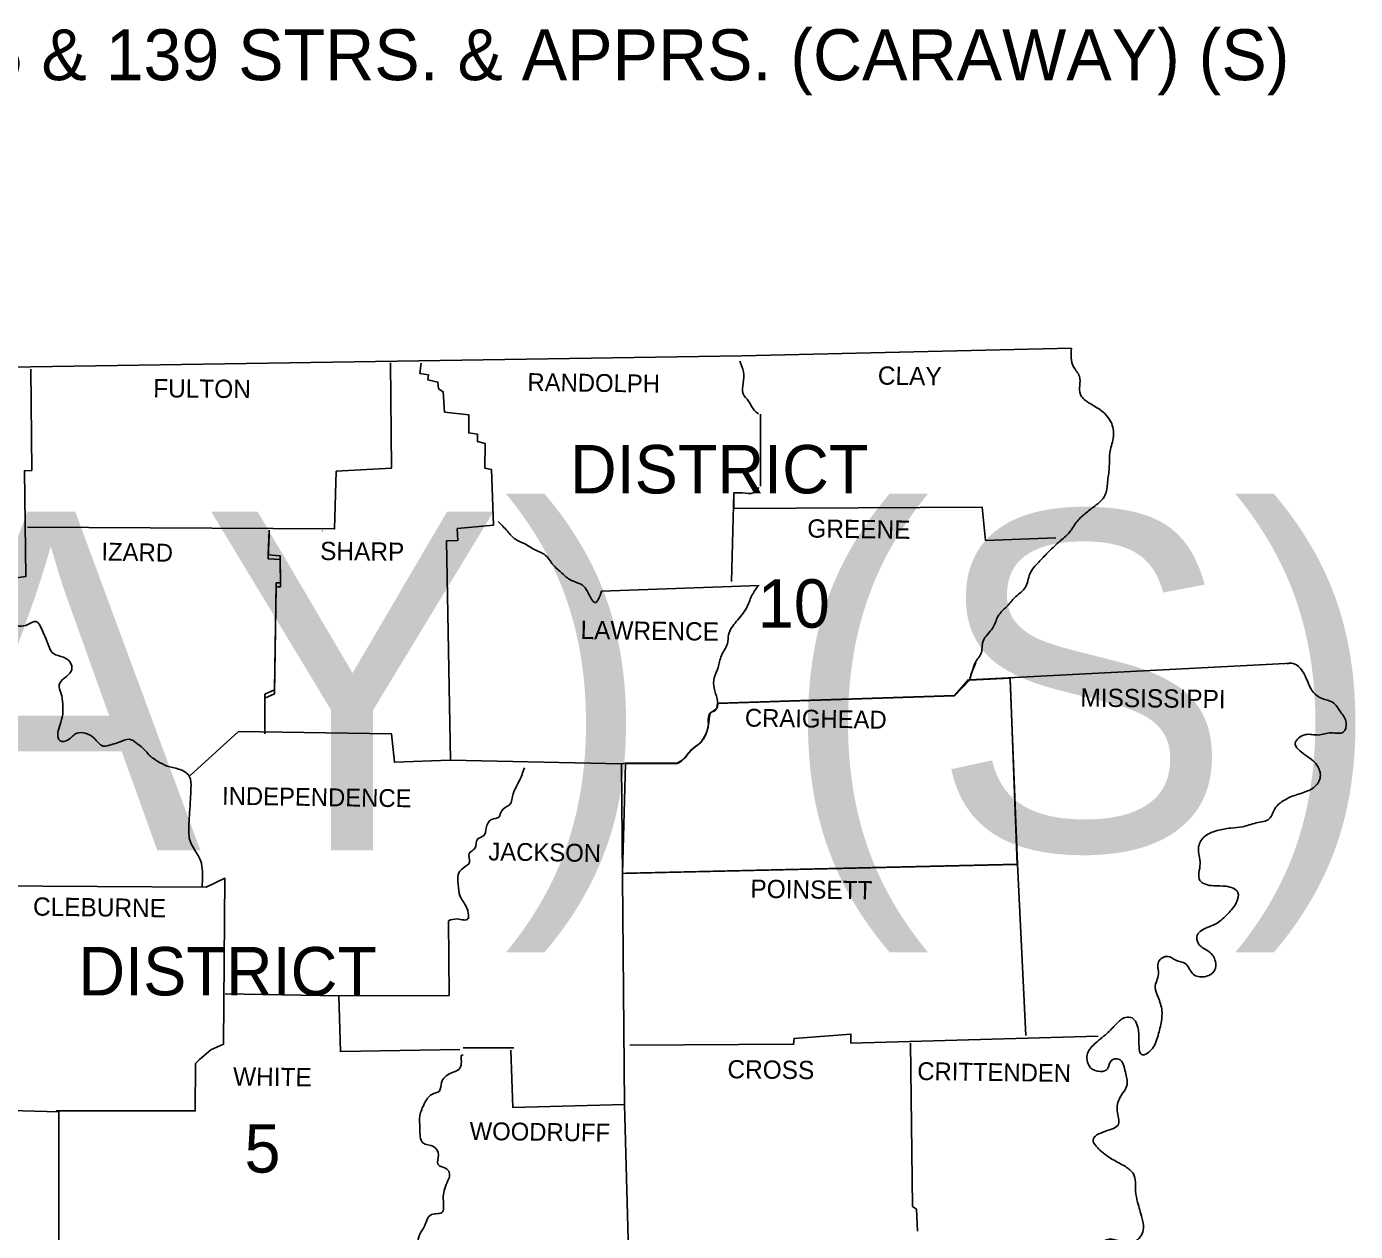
# Model space of a CAD drawing. Extents: x 166 to 3995, y -61 to 2074.
# Drawn here: x 2999.8 to 3305.9, y 1757.5 to 2035 of the extents above; entities that cross this region are included whole.
import ezdxf

# ---------------------------------------------------------------- set-up
doc = ezdxf.new("R2010")
doc.units = 0
for name, color, linetype in [('1', 7, 'Continuous'), ('2', 7, 'Continuous'), ('3', 7, 'Continuous'), ('R_Border', 7, 'Continuous'), ('S_MISC_BOUNDARY', 7, 'Continuous')]:
    doc.layers.add(name, color=color, linetype=linetype)

msp = doc.modelspace()

# ---------------------------------------------------------------- linework, layer by layer
at = {"layer": '1'}
for p, q in [((3216.98, 1884.51), (3218.15, 1888.13)), ((3217.27, 1885.68), (3218.45, 1888.52)), ((3100.35, 1799.78), (3112, 1799.78))]:
    msp.add_line(p, q, dxfattribs=at)
for points in [[(2703.71, 1956.42), (2861.92, 1956.32), (3000.75, 1956.61), (3164.54, 1959.16), (3240.46, 1960.92)], [(3083.62, 1957.49), (3083.82, 1933.23), (3071.1, 1932.55), (3070.71, 1919.24), (2999.97, 1919.63)], [(3090.67, 1957.4), (3090.37, 1955.05), (3092.33, 1954.76), (3092.23, 1953.58), (3094.48, 1953.09), (3094.68, 1951.53), (3095.75, 1950.84), (3096.05, 1946.15), (3101.63, 1945.56), (3101.63, 1941.35), (3103.68, 1941.06), (3103.68, 1939.39), (3105.44, 1938.9), (3105.34, 1933.23), (3106.91, 1932.94), (3107.3, 1920.12), (3098.98, 1919.34), (3099.08, 1916.6), (3096.54, 1916.5), (3097.42, 1866.01), (3136.85, 1865.13), (3137.53, 1786.66), (3111.8, 1785.98), (3111.31, 1799.19)], [(3000.75, 1956.03), (3000.95, 1932.74), (2999.28, 1932.64), (2999.58, 1908.28), (2992.73, 1907.3), (2993.32, 1900.75), (2995.66, 1897.71), (2995.47, 1889.98), (2982.16, 1889.5), (2981.67, 1877.56), (2969.54, 1877.17), (2968.95, 1862.69), (2969.64, 1861.51), (2969.93, 1838.42), (2990.87, 1837.05), (2990.58, 1785.49), (3007.21, 1785), (3007.21, 1732.56), (2994.1, 1731.58), (2993.12, 1720.04), (2971.11, 1719.94)], [(3168.84, 1945.66), (3168.84, 1929.12)], [(3162.19, 1907.11), (3162.68, 1927.56), (3162.68, 1923.94), (3219.91, 1924.23), (3220.7, 1916.6), (3236.84, 1917.18)], [(3055.64, 1918.95), (3055.44, 1913.27), (3058.18, 1913.07), (3058.28, 1906.81), (3057.3, 1906.81), (3056.91, 1882.16), (3054.66, 1881.18), (3054.66, 1872.96)], [(3055.64, 1918.06), (3055.44, 1912.39), (3058.18, 1912.19), (3058.28, 1905.93), (3057.3, 1905.93), (3056.91, 1881.28), (3054.66, 1880.3), (3054.66, 1872.08)], [(3067.87, 1918.75), (3067.97, 1918.85)], [(3132.25, 1904.95), (3168.55, 1906.23)], [(3216.98, 1884.51), (3291.24, 1888.32)], [(3159.25, 1879.12), (3213.55, 1880.89), (3216.78, 1884.6)], [(3226.37, 1884.41), (3228.04, 1842.04), (3229.99, 1802.61)], [(3037.44, 1862.49), (3048.6, 1872.57), (3083.82, 1872.08), (3084.5, 1865.52), (3097.32, 1866.01)], [(3149.67, 1865.33), (3137.73, 1865.33), (3136.85, 1865.13)], [(3228.04, 1842.04), (3137.92, 1839.99)], [(2990.87, 1837.05), (3041.16, 1836.76), (3045.46, 1838.81), (3045.17, 1800.56), (3042.24, 1799.29), (3039.59, 1797.04), (3038.71, 1796.16), (3038.62, 1785.2), (3006.62, 1785.2)], [(3096.93, 1829.03), (3097.12, 1811.81), (3071.69, 1811.71), (3045.56, 1812.2)], [(3071.69, 1811.71), (3072.08, 1798.89), (3099.57, 1799.38)], [(3138.71, 1800.36), (3176.47, 1800.56), (3176.57, 1801.93), (3189.68, 1802.91), (3189.68, 1800.85), (3246.63, 1802.42)], [(3203.38, 1800.85), (3203.87, 1763.18), (3204.75, 1762.6), (3205.04, 1757.51)], [(3100.35, 1798.11), (3099.86, 1798.01)], [(3137.53, 1786.66), (3139, 1733.05), (3115.71, 1732.95), (3115.62, 1730.8), (3108.87, 1730.41), (3108.28, 1719.25), (3100.06, 1719.25)]]:
    msp.add_lwpolyline(points, dxfattribs=at)
for points in [[(3240.46, 1960.92), (3240.95, 1956.61), (3242.32, 1954.36), (3242.52, 1950.25), (3244.18, 1948.49), (3247.02, 1946.73), (3249.56, 1943.89), (3250.15, 1940.57), (3249.36, 1937.14), (3249.17, 1933.33), (3248.78, 1930), (3248.19, 1926.97), (3245.84, 1924.52), (3243.59, 1922.76), (3241.54, 1920.71), (3240.07, 1918.55), (3237.53, 1916.21), (3234.98, 1913.76), (3232.93, 1911.61), (3230.87, 1908.87), (3229.89, 1905.83), (3227.64, 1903.68), (3225.88, 1901.73), (3223.53, 1899.08), (3222.36, 1896.44), (3220.11, 1893.41), (3219.62, 1890.47), (3218.15, 1888.13), (3218.06, 1887.73)], [(3164.05, 1957.89), (3164.93, 1955.44), (3164.83, 1952.8), (3164.83, 1950.35), (3166.1, 1948.69), (3167.37, 1946.63), (3168.35, 1945.75)], [(3168.45, 1928.83), (3167.18, 1927.56), (3164.73, 1927.56), (3162.68, 1927.56)], [(3108.38, 1921), (3110.53, 1918.75), (3112.39, 1916.89), (3114.54, 1915.81), (3117.08, 1914.35), (3119.33, 1913.17), (3120.8, 1911.31), (3122.86, 1909.26), (3124.91, 1907.6), (3128.14, 1906.03), (3129.22, 1904.37), (3130.68, 1902.31), (3132.25, 1904.95)], [(3168.25, 1906.13), (3166.79, 1903.78), (3165.61, 1901.04), (3163.26, 1897.91), (3161.5, 1894.88), (3161.21, 1892.82), (3159.84, 1890.08), (3159.06, 1887.34), (3158.18, 1884.99), (3158.18, 1882.55), (3158.86, 1880.1), (3158.67, 1877.85), (3157.2, 1876.78), (3156.81, 1873.94), (3156.22, 1871.98), (3154.95, 1870.03), (3153.09, 1868.56), (3151.13, 1866.31), (3149.67, 1865.33)], [(2995.66, 1897.71), (2999.58, 1897.03), (3001.93, 1897.91), (3003.59, 1895.37), (3004.47, 1893.41), (3005.94, 1890.57), (3008.29, 1889.69), (3010.05, 1888.13), (3010.05, 1886.46), (3008.48, 1884.9), (3007.31, 1883.33), (3007.7, 1881.47), (3008.09, 1878.93), (3008.09, 1876.48), (3007.5, 1874.23), (3007.01, 1872.18), (3007.5, 1870.42), (3009.36, 1870.71), (3011.32, 1872.18), (3013.37, 1872.18), (3015.33, 1871.1), (3017.38, 1869.24), (3019.44, 1869.63), (3021.1, 1870.12), (3023.45, 1870.81), (3025.11, 1869.93), (3026.58, 1868.75), (3028.34, 1866.89), (3030.01, 1865.72), (3032.16, 1864.64), (3034.8, 1863.96), (3037.25, 1862.3), (3037.64, 1859.46), (3037.54, 1857.01), (3037.34, 1853.98), (3037.15, 1850.65), (3037.44, 1847.42), (3038.52, 1845.27), (3039.89, 1842.73), (3040.28, 1840.38), (3040.18, 1836.66)], [(3290.16, 1888.22), (3291.24, 1888.32), (3294.57, 1884.8), (3296.03, 1881.86), (3298.19, 1880.2), (3300.63, 1879.32), (3302.49, 1877.07), (3303.76, 1874.62), (3303.08, 1872.47), (3300.34, 1872.28), (3297.31, 1871.79), (3294.37, 1871.88), (3292.02, 1869.93), (3294.18, 1867.29), (3297.01, 1864.84), (3297.8, 1862.2), (3296.23, 1859.65), (3293.1, 1858.28), (3290.07, 1857.11), (3287.33, 1854.76), (3286.05, 1852.51), (3283.02, 1851.53), (3279.89, 1850.65), (3277.15, 1850.36), (3274.02, 1849.77), (3270.99, 1848.3), (3269.72, 1845.76), (3270.11, 1842.14), (3270.01, 1838.32), (3273.24, 1837.05), (3276.08, 1836.95), (3278.81, 1835.49), (3278.52, 1833.33), (3276.47, 1830.6), (3274.02, 1828.44), (3271.57, 1827.37), (3269.32, 1825.31), (3270.11, 1823.26), (3272.16, 1821.89), (3273.63, 1819.64), (3273.43, 1817.58), (3271.09, 1816.11), (3268.54, 1816.7), (3266.68, 1819.15), (3264.53, 1819.93), (3262.67, 1820.81), (3260.52, 1819.54), (3260.52, 1816.7), (3259.74, 1813.67), (3260.42, 1811.42), (3261.3, 1808.29), (3261.2, 1805.94), (3260.42, 1802.61), (3258.76, 1799.19), (3256.8, 1798.11), (3256.02, 1801.83), (3255.63, 1804.86), (3254.45, 1806.62), (3252.89, 1806.72), (3250.83, 1805.25), (3248.58, 1803), (3245.74, 1800.56), (3244.08, 1798.11), (3244.96, 1795.08), (3247.11, 1794.3), (3248.78, 1794.88), (3249.66, 1796.84), (3251.32, 1797.13), (3252.89, 1794.1)], [(3114.44, 1864.25), (3113.27, 1861.22), (3111.9, 1858.28), (3111.02, 1855.74), (3109.16, 1854.27), (3108.57, 1852.9), (3106.91, 1852.32), (3105.64, 1850.36), (3105.05, 1848.6), (3103.68, 1847.82), (3103, 1845.66), (3101.72, 1844.49), (3101.82, 1842.53), (3100.35, 1841.16), (3099.18, 1839.6), (3099.18, 1837.44), (3099.67, 1834.61), (3100.65, 1832.94), (3101.53, 1830.79), (3101.43, 1829.42), (3098.98, 1829.42), (3096.93, 1829.03)], [(3099.86, 1798.01), (3099.37, 1794.79), (3097.52, 1793.91), (3095.36, 1791.75), (3094.87, 1789.8), (3093.11, 1789.01), (3091.45, 1786.96), (3090.37, 1784.12), (3090.37, 1781.19), (3091.06, 1777.86), (3093.5, 1776.98), (3094.68, 1775.02), (3094.48, 1772.97), (3096.83, 1771.6), (3097.22, 1770.42), (3096.83, 1769.15), (3095.75, 1765.53), (3095.85, 1763.09), (3095.66, 1762.01), (3093.02, 1761.32), (3091.45, 1758.68), (3090.37, 1756.82), (3089.98, 1754.38), (3090.28, 1752.62), (3089.49, 1751.25), (3089.2, 1749.19), (3088.22, 1747.43), (3087.34, 1745.77), (3088.32, 1743.81), (3088.03, 1742.44), (3087.44, 1740.29), (3087.93, 1739.6)], [(3252.89, 1794.1), (3253.28, 1791.26), (3251.62, 1788.23), (3251.03, 1785.2), (3251.32, 1782.16), (3248.19, 1780.5), (3245.45, 1778.54), (3247.02, 1776.2), (3249.95, 1774.04), (3252.89, 1772.38), (3254.75, 1770.72), (3255.24, 1766.71), (3255.72, 1764.16), (3256.7, 1760.64), (3257.09, 1758.19), (3255.33, 1755.26), (3253.28, 1754.67), (3251.13, 1755.36), (3248.58, 1755.55), (3246.53, 1753.59), (3245.06, 1750.86), (3243.59, 1748.12), (3242.52, 1745.77), (3241.44, 1743.22), (3239.29, 1740.29), (3236.65, 1739.8), (3233.51, 1739.02), (3231.66, 1736.86), (3231.95, 1733.24), (3233.71, 1730.8), (3235.08, 1727.76), (3236.06, 1725.12), (3235.57, 1721.8), (3234.2, 1719.35), (3232.44, 1717.88), (3231.66, 1714.75), (3230.38, 1712.4), (3229.21, 1711.62), (3226.86, 1711.82), (3224.32, 1712.31), (3222.16, 1712.11), (3220.11, 1711.03), (3218.06, 1711.72), (3215.9, 1714.07), (3214.14, 1715.83), (3212.19, 1716.51), (3210.13, 1715.44), (3209.74, 1712.21), (3210.72, 1708.88), (3211.6, 1704.38), (3210.72, 1701.64), (3210.42, 1697.14)]]:
    msp.add_spline(points, degree=3, dxfattribs=at)
at = {"layer": 'S_MISC_BOUNDARY'}
for p, q in [((3216.98, 1884.42), (3213.56, 1880.8)), ((3213.56, 1880.8), (3158.92, 1879.03)), ((3137.73, 1865.24), (3137.07, 1839.88)), ((3149.67, 1865.24), (3137.73, 1865.24)), ((3137.07, 1839.88), (3227.95, 1841.96))]:
    msp.add_line(p, q, dxfattribs=at)
msp.add_lwpolyline([(3227.95, 1841.96), (3226.35, 1884.9), (3216.98, 1884.42)], dxfattribs=at)
msp.add_spline([(3158.92, 1879.03), (3158.89, 1878.71), (3158.84, 1878.39), (3158.77, 1878.08), (3158.67, 1877.77), (3158.38, 1877.43), (3157.92, 1877.23), (3157.47, 1877.02), (3157.2, 1876.69), (3157.13, 1876.34), (3157.07, 1875.99), (3157, 1875.27), (3156.94, 1874.56), (3156.81, 1873.85), (3156.55, 1872.87), (3156.22, 1871.9), (3155.68, 1870.86), (3155.34, 1870.38), (3154.95, 1869.94), (3154.51, 1869.54), (3154.02, 1869.19), (3153.54, 1868.85), (3153.09, 1868.47), (3152.59, 1867.93), (3152.12, 1867.35), (3151.65, 1866.77), (3151.14, 1866.22), (3150.45, 1865.68), (3150.07, 1865.45), (3149.67, 1865.24)], degree=3, dxfattribs=at)

# ---------------------------------------------------------------- texts
at = {"layer": '2'}
for s, height, rotation, p in [('CLAY', 4.206, 359.2258, (3195.85, 1952.5)), ('FULTON', 4.206, 359.4996, (3028.93, 1949.57)), ('RANDOLPH', 4.109, 359.2583, (3115.13, 1951.04)), ('GREENE', 4.207, 359.2361, (3179.6, 1917.28)), ('SHARP', 4.206, 359.3905, (3067.38, 1912.1)), ('IZARD', 4.108, 358.9258, (3016.99, 1912)), ('LAWRENCE', 4.207, 359.2678, (3127.36, 1893.9)), ('MISSISSIPPI', 4.2062, 359.3097, (3242.52, 1878.34)), ('CRAIGHEAD', 4.109, 359.1159, (3165.22, 1873.74)), ('INDEPENDENCE', 4.1081, 359.2187, (3044.78, 1855.74)), ('JACKSON', 4.108, 359.1352, (3106.13, 1842.92)), ('POINSETT', 4.206, 359.1987, (3166.49, 1834.31)), ('CLEBURNE', 4.206, 359.2535, (3001.24, 1830.2)), ('CROSS', 4.206, 359.3839, (3161.21, 1792.73)), ('WHITE', 4.207, 359.3139, (3047.32, 1791.07)), ('CRITTENDEN', 4.109, 359.213, (3204.94, 1792.34)), ('WOODRUFF', 4.108, 359.2748, (3101.82, 1778.54))]:
    msp.add_text(s, height=height, rotation=rotation, dxfattribs=at).set_placement(p)
msp.add_text('HWYS. 135 & 139 STRS.  & APPRS. (CARAWAY) (S)', height=78, dxfattribs=at).set_placement((796.83, 1845.2))
at = {"layer": '3'}
for s, height, p in [('DISTRICT', 11.154, (3124.93, 1927.43)), ('10', 11.154, (3168.23, 1896.51)), ('DISTRICT', 11.154, (3011.71, 1811.81)), ('5', 11.15, (3049.97, 1771.01))]:
    msp.add_text(s, height=height, dxfattribs=at).set_placement(p)
at = {"layer": 'R_Border'}
msp.add_text('HWYS. 135 & 139 STRS. & APPRS. (CARAWAY) (S)', height=11.724, dxfattribs=at).set_placement((2916.93, 2022.61))

doc.saveas('drawing.dxf')
